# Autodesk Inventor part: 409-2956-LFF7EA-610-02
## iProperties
Created: 2011-01
Part Number: 409-2956-LFF7EA-610-02
Cost Center: 0 lbmass
Material: A36 STEEL PLATE
Document SubType Name: Sheet Metal
Designer: S. Boerckel
Authority: 0 in^3
Mass: 1748.62 g
Surface Area: 976.22 cm^2
Volume: 222.471 cm^3
Density: 7.86 g/cm^3
Flat Pattern Width: 17.78 cm
Flat Pattern Length: 26.1089 cm
Flat Pattern Area: 464.217 cm^2
Sheet Metal Rule: 3/16"Thk
Description: VERTICAL SUPPORT PLATE
SaveDate: 2008-01-15
SaveTime: 10:24
FileName: Sheet Metal
Wide: =<Flat Pattern Width>cm
Length: =<Flat Pattern Length>cm
Thickness: 0.1875 in
SMR: =<Sheet Metal Rule> - <Material>
Author: S. Boerckel
Revision Number: 0
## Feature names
1. Plate1
2. Plate2
3. Bend1
